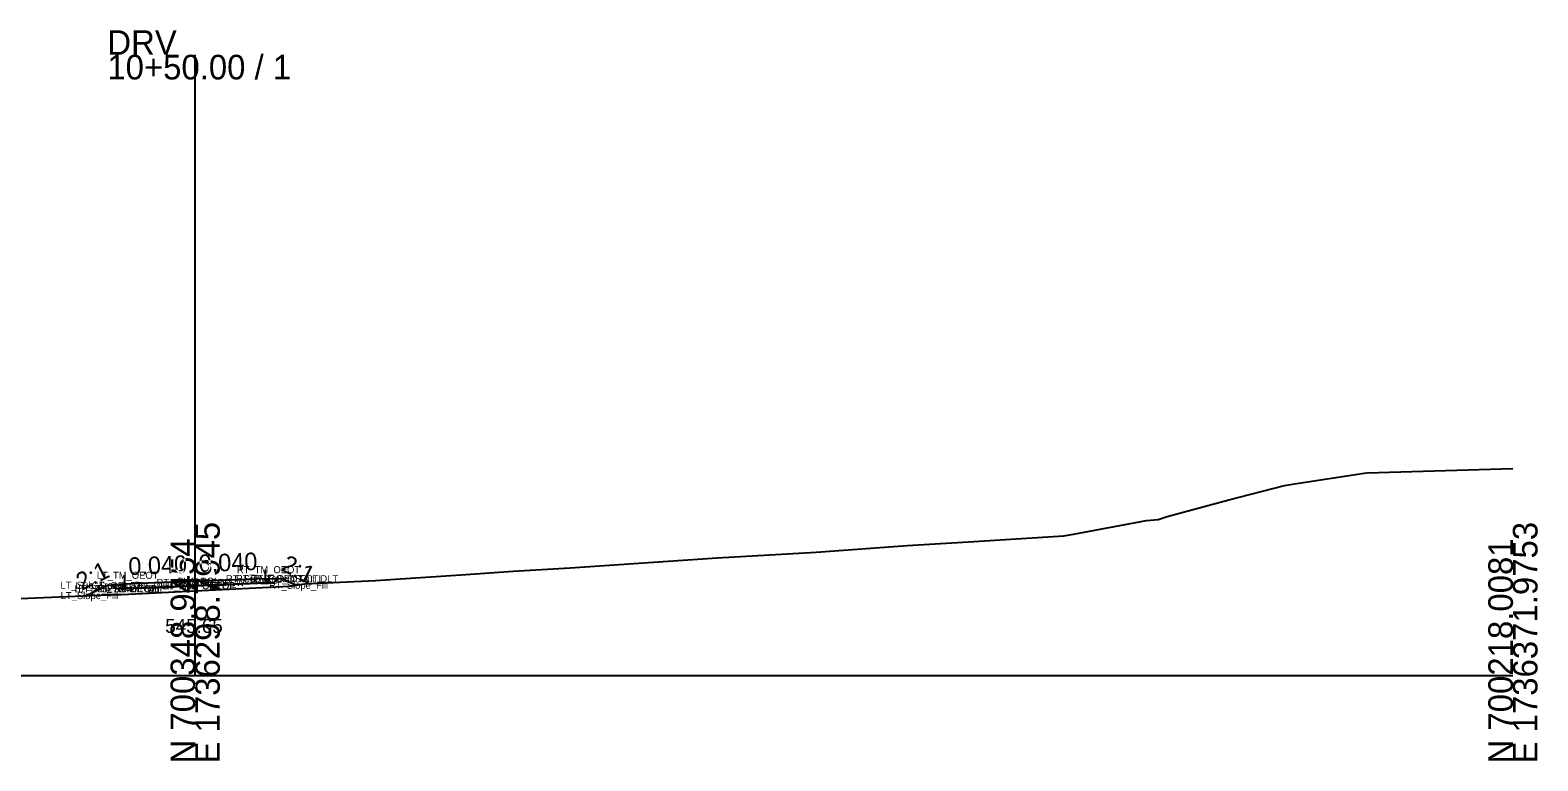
# Model space of a CAD drawing. Extents: x -26 to 803, y -10 to 646.
# Drawn here: x 631.2 to 802.8, y 190.3 to 273.4 of the extents above; entities that cross this region are included whole.
import ezdxf

# ---------------------------------------------------------------- set-up
doc = ezdxf.new("R2010")
doc.units = 0
for name, color, linetype in [('Default', 7, 'Continuous'), ('Exist Cross Section Cell', 7, 'Continuous'), ('Exist XS Center Line Elevation Label', 7, 'Continuous'), ('Exist XS Ground Line', 7, 'Continuous'), ('Prop CMT Pvmt Course 1', 7, 'Continuous'), ('Prop CMT Pvmt Course 2', 7, 'Continuous'), ('Prop CMT Pvmt Surface', 7, 'Continuous'), ('Prop CMT Pvmt Surface Overlay', 7, 'Continuous'), ('Prop CMT Shld Paved Course 1', 7, 'Continuous'), ('Prop CMT Shld Paved Course 2', 7, 'Continuous'), ('Prop CMT Slope Grass', 7, 'Continuous'), ('Prop CMT Subgrade Earthwork', 7, 'Continuous'), ('Prop XS EOT Tick Mark', 7, 'Continuous'), ('Prop XS SE Text', 7, 'Continuous'), ('Prop XS Side Slope Text', 7, 'Continuous')]:
    doc.layers.add(name, color=color, linetype=linetype)

msp = doc.modelspace()

# ---------------------------------------------------------------- linework, layer by layer
at = {"layer": 'Exist Cross Section Cell'}
for p, q in [((650, 200), (650, 270.61)), ((500, 200), (650, 200)), ((650, 200), (800, 200))]:
    msp.add_line(p, q, dxfattribs=at)
at = {"layer": 'Exist XS Ground Line'}
for p, q in [((783.4, 223.05), (800, 223.54)), ((767.68, 220), (774.01, 221.61)), ((774.01, 221.61), (775.15, 221.82)), ((775.15, 221.82), (783.06, 223.03)), ((783.06, 223.03), (783.4, 223.05)), ((760.63, 218.11), (767.68, 220)), ((759.62, 217.77), (760.63, 218.11)), ((749.97, 216.1), (758.28, 217.64)), ((758.28, 217.64), (759.62, 217.77)), ((720.69, 214.04), (731.04, 214.81)), ((731.04, 214.81), (738.02, 215.23)), ((738.02, 215.23), (748.88, 215.9)), ((748.88, 215.9), (749.97, 216.1)), ((692.7, 212.26), (709.43, 213.39)), ((709.43, 213.39), (720.69, 214.04)), ((670.51, 210.81), (680.82, 211.51)), ((680.82, 211.51), (686.18, 211.87)), ((686.18, 211.87), (692.7, 212.26)), ((641.66, 209.24), (650, 209.65)), ((650, 209.65), (660.74, 210.17)), ((660.74, 210.17), (662.5, 210.42)), ((662.5, 210.42), (670.51, 210.81)), ((625.77, 208.61), (640.8, 209.23)), ((640.8, 209.23), (641.66, 209.24))]:
    msp.add_line(p, q, dxfattribs=at)
at = {"layer": 'Prop CMT Pvmt Course 1'}
for points in [[(650, 210.73), (642, 210.41)], [(642, 210.41), (642, 209.91)], [(642, 209.91), (650, 210.23)], [(650, 210.73), (658, 211.05)], [(650, 210.6), (650, 210.73)], [(650, 210.6), (650, 210.73)], [(650, 210.23), (650, 210.6), (650, 210.6)], [(650, 210.23), (650, 210.6), (650, 210.6)], [(658, 210.55), (650, 210.23)], [(658, 211.05), (658, 210.55)]]:
    msp.add_lwpolyline(points, dxfattribs=at)
at = {"layer": 'Prop CMT Pvmt Course 2'}
for points in [[(642, 209.91), (650, 210.23)], [(650, 210.23), (642, 209.91)], [(642, 209.91), (642, 209.91)], [(658, 210.55), (650, 210.23)], [(650, 210.23), (658, 210.55)], [(650, 210.23), (650, 210.23)], [(650, 210.23), (650, 210.23)], [(658, 210.55), (658, 210.55)]]:
    msp.add_lwpolyline(points, dxfattribs=at)
at = {"layer": 'Prop CMT Pvmt Surface'}
for points in [[(650, 210.73), (642, 210.41)], [(650, 210.73), (658, 211.05)]]:
    msp.add_lwpolyline(points, dxfattribs=at)
at = {"layer": 'Prop CMT Pvmt Surface Overlay'}
for points in [[(650, 210.73), (642, 210.41)], [(650, 210.73), (658, 211.05)]]:
    msp.add_lwpolyline(points, dxfattribs=at)
at = {"layer": 'Prop CMT Shld Paved Course 1'}
for points in [[(642, 210.41), (641.48, 209.89)], [(641.48, 209.89), (642, 209.91)], [(642, 209.91), (642, 210.41)], [(658, 211.05), (658.48, 210.57)], [(658, 210.55), (658, 211.05)], [(658.48, 210.57), (658, 210.55)]]:
    msp.add_lwpolyline(points, dxfattribs=at)
at = {"layer": 'Prop CMT Shld Paved Course 2'}
for points in [[(642, 209.91), (641.48, 209.89), (640.98, 209.87)], [(640.98, 209.87), (642, 209.91)], [(640.98, 209.87), (640.98, 209.87)], [(642, 209.91), (642, 209.91)], [(658, 210.55), (658.48, 210.57), (658.98, 210.59)], [(658.98, 210.59), (658, 210.55)], [(658, 210.55), (658, 210.55)], [(658.98, 210.59), (658.98, 210.59)]]:
    msp.add_lwpolyline(points, dxfattribs=at)
at = {"layer": 'Prop CMT Slope Grass'}
for points in [[(642, 210.41), (640, 210.25), (637.7, 209.1)], [(658, 211.05), (660, 211.01), (661.47, 210.27)]]:
    msp.add_lwpolyline(points, dxfattribs=at)
at = {"layer": 'Prop CMT Subgrade Earthwork'}
for points in [[(650, 210.23), (642, 209.91), (640.98, 209.87), (640.55, 210.29)], [(650, 210.23), (658, 210.55), (658.98, 210.59), (659.41, 211.02)]]:
    msp.add_lwpolyline(points, dxfattribs=at)
at = {"layer": 'Prop XS EOT Tick Mark'}
for points in [[(642, 210.41), (642, 211.41)], [(658, 211.05), (658, 212.05)]]:
    msp.add_lwpolyline(points, dxfattribs=at)

# ---------------------------------------------------------------- texts
at = {"layer": 'Default'}
for s, p in [('LT_TM_OEOT', (638.8, 211.01)), ('LT_TM_OEOT', (638.8, 211.01)), ('PV1_PGL', (647.98, 210.33)), ('PV1_PGL', (647.98, 210.33)), ('RT_Sub_Trench_Out_DLT', (653.49, 210.62)), ('RT_Sub_Trench_Out_DLT', (653.49, 210.62)), ('RT_PV1_OEOT', (654.64, 210.65)), ('RT_PV1_OEOT', (654.64, 210.65)), ('RT_TM_OEOT', (654.75, 211.65)), ('RT_TM_OEOT', (654.75, 211.65)), ('RT_GS_OS_CTL', (656.32, 210.61)), ('RT_GS_OS_CTL', (656.32, 210.61)), ('LT_Sub_Trench_Out_DLT', (634.67, 209.89)), ('LT_Sub_Trench_Out_DLT', (634.67, 209.89)), ('LT_Slope_Fill', (634.69, 208.7)), ('LT_Slope_Fill', (634.69, 208.7)), ('LT_Sub_Trench_Out', (636.27, 209.47)), ('LT_Sub_Trench_Out', (636.27, 209.47)), ('LT_GS_OS_CTL', (636.37, 209.85)), ('LT_GS_OS_CTL', (636.37, 209.85)), ('LT_PS2_Shelf_Out', (636.7, 209.47)), ('LT_PS2_Shelf_Out', (636.7, 209.47)), ('LT_PS2_OEOP', (638.11, 209.49)), ('LT_PS2_OEOP', (638.11, 209.49)), ('LT_PV2_OEOT', (638.6, 209.51)), ('LT_PV2_OEOT', (638.6, 209.51)), ('LT_Sub_OEOT', (638.62, 209.51)), ('LT_Sub_OEOT', (638.62, 209.51)), ('LT_PV1_OEOT', (638.69, 210.01)), ('LT_PV1_OEOT', (638.69, 210.01)), ('RT_PV1_OEEOP_W', (645.6, 210.2)), ('RT_PV1_OEEOP_W', (645.6, 210.2)), ('LT_PV1_OEEOP_W', (645.64, 210.2)), ('LT_PV1_OEEOP_W', (645.64, 210.2)), ('RT_PV2_OEEOP', (646.27, 209.83)), ('RT_PV2_OEEOP', (646.27, 209.83)), ('RT_Sub_OEEOP', (646.29, 209.83)), ('RT_Sub_OEEOP', (646.29, 209.83)), ('LT_PV2_OEEOP', (646.31, 209.83)), ('LT_PV2_OEEOP', (646.31, 209.83)), ('LT_Sub_OEEOP', (646.33, 209.83)), ('LT_Sub_OEEOP', (646.33, 209.83)), ('PV1_PGL_W', (647.21, 210.2)), ('PV1_PGL_W', (647.21, 210.2)), ('RT_Sub_Trench_Out', (654.22, 210.19)), ('RT_Sub_Trench_Out', (654.22, 210.19)), ('RT_PV2_OEOT', (654.55, 210.15)), ('RT_PV2_OEOT', (654.55, 210.15)), ('RT_Sub_OEOT', (654.57, 210.15)), ('RT_Sub_OEOT', (654.57, 210.15)), ('RT_PS2_Shelf_Out', (654.66, 210.19)), ('RT_PS2_Shelf_Out', (654.66, 210.19)), ('RT_PS2_OEOP', (655.06, 210.17)), ('RT_PS2_OEOP', (655.06, 210.17)), ('RT_Slope_Fill', (658.41, 209.87)), ('RT_Slope_Fill', (658.41, 209.87))]:
    msp.add_text(s, height=0.8, dxfattribs=at).set_placement(p)
at = {"layer": 'Exist Cross Section Cell'}
for s, p in [('DRV', (640, 270.61)), ('10+50.00 / 1', (640, 267.81))]:
    msp.add_text(s, height=2.8, dxfattribs=at).set_placement(p)
for s, p in [('E 1736298.7945', (652.8, 190)), ('E 1736371.9753', (802.8, 190)), ('N 700348.9454', (650, 190)), ('N 700218.0081', (800, 190))]:
    msp.add_text(s, height=2.8, rotation=90, dxfattribs=at).set_placement(p)
at = {"layer": 'Exist XS Center Line Elevation Label'}
msp.add_text('545.65', height=1.6, dxfattribs=at).set_placement((646.59, 204.85))
at = {"layer": 'Prop XS SE Text'}
for p in [(642.43, 211.43), (650.43, 211.75)]:
    msp.add_text('0.040', height=2, rotation=2.2906, dxfattribs=at).set_placement(p)
at = {"layer": 'Prop XS Side Slope Text'}
for rotation, p in [(26.5651, (637.08, 209.63)), (333.4349, (659.64, 212.03))]:
    msp.add_text('2:1', height=2, rotation=rotation, dxfattribs=at).set_placement(p)

doc.saveas('drawing.dxf')
